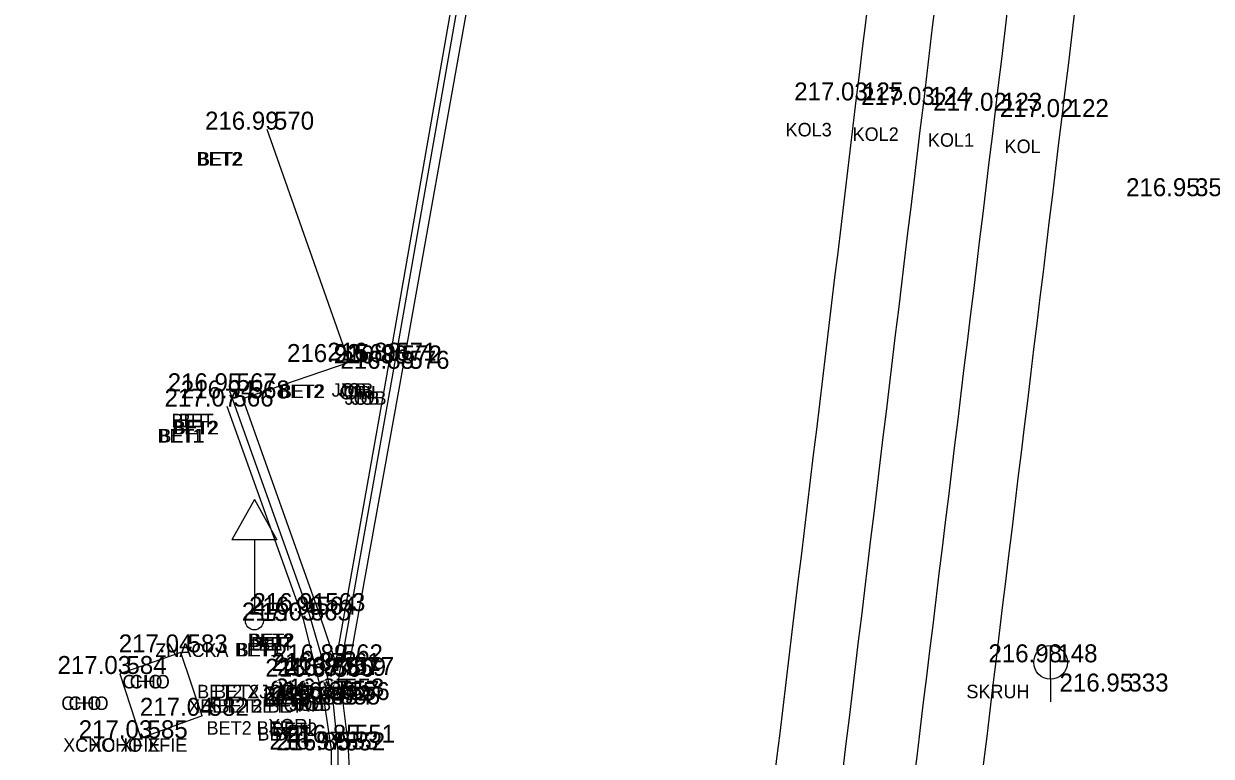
# Model space of a CAD drawing. Extents: x -471047 to -470889, y -1102859 to -1102000.
# Drawn here: x -471013.41 to -470987.01, y -1102709.11 to -1102692.81 of the extents above; entities that cross this region are included whole.
import ezdxf

# ---------------------------------------------------------------- set-up
doc = ezdxf.new("R2010")
doc.units = 0
for name, color, linetype in [('Vrstva 1', 7, 'Continuous'), ('Vrstva 19', 7, 'Continuous'), ('Vrstva 20', 7, 'Continuous'), ('Vrstva 25', 7, 'Continuous'), ('Vrstva 34', 7, 'Continuous'), ('Vrstva 35', 7, 'Continuous'), ('Vrstva 36', 7, 'Continuous'), ('Vrstva 38', 7, 'Continuous'), ('Vrstva 5', 7, 'Continuous'), ('Vrstva 7', 7, 'Continuous'), ('Vrstva 8', 7, 'Continuous')]:
    doc.layers.add(name, color=color, linetype=linetype)

msp = doc.modelspace()

# ---------------------------------------------------------------- linework, layer by layer
at = {"layer": 'Vrstva 1'}
for points in [[(-471040.344, -1102858.385), (-471031.676, -1102846.187), (-471026.357, -1102838.629), (-471023.212, -1102833.975), (-471019.21, -1102827.465), (-471016.861, -1102823.272), (-471013.099, -1102815.912), (-471010.824, -1102810.955), (-471007.329, -1102802.292), (-471005.34, -1102796.515), (-471002.842, -1102787.838), (-471001.3, -1102780.997), (-471000.19, -1102774.713), (-470999.247, -1102768.204), (-470998.794, -1102764.784), (-470997.199, -1102751.812), (-470994.899, -1102732.807), (-470992.551, -1102713.262), (-470990.326, -1102694.887), (-470988.122, -1102676.57), (-470985.812, -1102657.305), (-470983.537, -1102638.407), (-470981.386, -1102620.622), (-470979.843, -1102608.014), (-470976.377, -1102579.253), (-470972.945, -1102550.69), (-470970.475, -1102530.206), (-470967.905, -1102508.801), (-470965.053, -1102485.131), (-470962.734, -1102465.9), (-470960.173, -1102444.812), (-470957.795, -1102425.103), (-470954.965, -1102401.839), (-470953.834, -1102392.574), (-470952.33, -1102379.985), (-470950.744, -1102366.853), (-470948.978, -1102352.106), (-470947.037, -1102335.844), (-470944.949, -1102318.462), (-470944.013, -1102310.745), (-470942.39, -1102297.267), (-470939.519, -1102273.45), (-470937.593, -1102257.43), (-470936.064, -1102244.81), (-470934.114, -1102228.634), (-470931.621, -1102207.856), (-470929.536, -1102190.857), (-470926.572, -1102166.31), (-470924.91, -1102152.663), (-470923.413, -1102140.333), (-470921.923, -1102127.669), (-470921.155, -1102120.084), (-470920.446, -1102109.574), (-470919.912, -1102099.137), (-470919.63, -1102088.981), (-470919.523, -1102081.193), (-470919.563, -1102070.395), (-470919.714, -1102064.236), (-470920.134, -1102054.704), (-470920.462, -1102047.615), (-470920.599, -1102044.52), (-470920.743, -1102041.873), (-470921.125, -1102034.455), (-470921.774, -1102030.337), (-470922.418, -1102027.787), (-470923.734, -1102023.93), (-470924.872, -1102021.434), (-470926.752, -1102018.182), (-470927.953, -1102016.45), (-470929.616, -1102014.424), (-470932.252, -1102011.756), (-470935.111, -1102009.425), (-470938.391, -1102007.371), (-470942.651, -1102005.401)], [(-471041.328, -1102857.18), (-471032.144, -1102844.242), (-471027.583, -1102837.763), (-471024.388, -1102833.028), (-471020.451, -1102826.6), (-471018.089, -1102822.378), (-471014.542, -1102815.445), (-471012.233, -1102810.418), (-471009.247, -1102803.108), (-471006.795, -1102796.098), (-471004.315, -1102787.532), (-471002.782, -1102780.723), (-471001.674, -1102774.458), (-471000.75, -1102768.095), (-471000.28, -1102764.601), (-470998.692, -1102751.741), (-470996.378, -1102732.635), (-470994.028, -1102713.058), (-470991.808, -1102694.749), (-470989.616, -1102676.447), (-470987.284, -1102657.013), (-470985.031, -1102638.272), (-470982.87, -1102620.431), (-470981.334, -1102607.933), (-470977.881, -1102579.263), (-470974.429, -1102550.492), (-470971.964, -1102530.054), (-470969.391, -1102508.607), (-470966.54, -1102484.984), (-470964.231, -1102465.853), (-470961.679, -1102444.752), (-470959.304, -1102425.078), (-470956.455, -1102401.634), (-470955.339, -1102392.489), (-470953.812, -1102379.71), (-470952.249, -1102366.808), (-470950.479, -1102352.023), (-470948.536, -1102335.868), (-470946.426, -1102318.233), (-470945.493, -1102310.531), (-470943.864, -1102297.013), (-470940.984, -1102273.071), (-470939.078, -1102257.195), (-470937.559, -1102244.684), (-470935.592, -1102228.353), (-470933.101, -1102207.653), (-470931.011, -1102190.57), (-470928.046, -1102166.021), (-470926.409, -1102152.578), (-470924.898, -1102140.121), (-470923.427, -1102127.544), (-470922.647, -1102119.826), (-470921.919, -1102109.229), (-470921.42, -1102099.134), (-470921.127, -1102089.016), (-470921.023, -1102081.453), (-470921.061, -1102070.468), (-470921.209, -1102064.314), (-470921.666, -1102053.966), (-470922.156, -1102043.345), (-470922.299, -1102039.934), (-470922.637, -1102034.36), (-470923.091, -1102031.241), (-470923.847, -1102028.247), (-470925.083, -1102024.594), (-470926.222, -1102022.086), (-470928.04, -1102018.943), (-470929.138, -1102017.357), (-470930.929, -1102015.175), (-470933.062, -1102013.049), (-470936.379, -1102010.368), (-470939.169, -1102008.662), (-470942.899, -1102006.906), (-470945.661, -1102005.908)], [(-471043.557, -1102855.955), (-471035.129, -1102844.026), (-471029.872, -1102836.499), (-471026.577, -1102831.578), (-471022.675, -1102825.415), (-471020.123, -1102821.053), (-471016.667, -1102814.59), (-471014.208, -1102809.45), (-471011.177, -1102802.451), (-471008.55, -1102795.333), (-471006.082, -1102787.209), (-471004.464, -1102780.376), (-471003.265, -1102774.167), (-471002.327, -1102767.948), (-471001.636, -1102762.527), (-471000.297, -1102751.605), (-470997.959, -1102732.524), (-470995.602, -1102712.802), (-470993.412, -1102694.623), (-470991.21, -1102676.17), (-470988.891, -1102656.857), (-470986.625, -1102638.083), (-470984.455, -1102620.195), (-470982.936, -1102607.733), (-470979.497, -1102579.223), (-470976.023, -1102550.279), (-470973.554, -1102529.822), (-470970.991, -1102508.497), (-470968.146, -1102484.787), (-470965.835, -1102465.72), (-470963.284, -1102444.529), (-470960.91, -1102424.942), (-470958.043, -1102401.343), (-470956.946, -1102392.356), (-470955.396, -1102379.408), (-470953.851, -1102366.636), (-470952.049, -1102351.733), (-470950.124, -1102335.611), (-470948.034, -1102318.083), (-470947.094, -1102310.328), (-470945.421, -1102296.51), (-470942.58, -1102272.848), (-470940.675, -1102256.948), (-470939.176, -1102244.526), (-470937.187, -1102228.174), (-470934.708, -1102207.467), (-470932.621, -1102190.433), (-470929.634, -1102165.778), (-470928.004, -1102152.415), (-470926.45, -1102139.595), (-470925.003, -1102127.418), (-470924.249, -1102119.695), (-470923.515, -1102109.093), (-470923.018, -1102099.069), (-470922.711, -1102088.911), (-470922.643, -1102081.356), (-470922.797, -1102070.414), (-470923.018, -1102064.454), (-470923.52, -1102053.203), (-470923.823, -1102047.529), (-470924.123, -1102041.506), (-470924.462, -1102037.486), (-470924.934, -1102031.904), (-470925.664, -1102028.672), (-470926.771, -1102025.506), (-470927.959, -1102022.914), (-470929.674, -1102020.028), (-470930.76, -1102018.498), (-470932.447, -1102016.478), (-470935.215, -1102013.816), (-470937.644, -1102011.98), (-470940.381, -1102010.371), (-470943.968, -1102008.669), (-470947.145, -1102007.524), (-470950.874, -1102006.74)], [(-471044.756, -1102855.056), (-471036.376, -1102843.177), (-471031.167, -1102835.741), (-471027.859, -1102830.8), (-471023.934, -1102824.593), (-471021.43, -1102820.312), (-471018.011, -1102813.91), (-471015.536, -1102808.75), (-471012.578, -1102801.897), (-471009.95, -1102794.77), (-471007.561, -1102786.914), (-471005.936, -1102780.074), (-471004.727, -1102773.818), (-471003.828, -1102767.827), (-471003.121, -1102762.345), (-471001.787, -1102751.467), (-470999.446, -1102732.348), (-470997.073, -1102712.539), (-470994.902, -1102694.521), (-470992.696, -1102676.023), (-470990.376, -1102656.68), (-470988.131, -1102638.071), (-470985.947, -1102620.018), (-470984.417, -1102607.512), (-470980.993, -1102579.08), (-470977.514, -1102550.137), (-470975.048, -1102529.649), (-470972.488, -1102508.37), (-470969.618, -1102484.508), (-470967.34, -1102465.669), (-470964.767, -1102444.39), (-470962.402, -1102424.781), (-470959.534, -1102401.193), (-470958.432, -1102392.151), (-470956.883, -1102379.208), (-470955.335, -1102366.424), (-470953.535, -1102351.506), (-470951.606, -1102335.399), (-470949.519, -1102317.94), (-470948.575, -1102310.159), (-470946.889, -1102296.144), (-470944.056, -1102272.618), (-470942.139, -1102256.659), (-470940.657, -1102244.341), (-470938.638, -1102227.749), (-470936.19, -1102207.298), (-470934.102, -1102190.255), (-470931.124, -1102165.639), (-470929.492, -1102152.254), (-470927.915, -1102139.252), (-470926.46, -1102127.103), (-470925.74, -1102119.604), (-470925.012, -1102108.913), (-470924.523, -1102099.054), (-470924.217, -1102088.866), (-470924.148, -1102081.334), (-470924.301, -1102070.391), (-470924.518, -1102064.43), (-470924.97, -1102054.435), (-470925.588, -1102041.569), (-470925.963, -1102035.313), (-470926.405, -1102032.225), (-470927.078, -1102029.198), (-470928.123, -1102026.148), (-470929.318, -1102023.558), (-470930.84, -1102020.97), (-470931.868, -1102019.515), (-470933.443, -1102017.605), (-470936.26, -1102014.885), (-470938.429, -1102013.255), (-470941.213, -1102011.639), (-470944.847, -1102009.927), (-470947.723, -1102008.912), (-470951.444, -1102008.161), (-470954.511, -1102007.931), (-470957.895, -1102008.041)]]:
    msp.add_spline(points, degree=3, dxfattribs=at)
at = {"layer": 'Vrstva 19'}
for p, q in [((-471008.287, -1102703.398), (-471008.787, -1102704.298)), ((-471008.287, -1102703.398), (-471007.787, -1102704.298)), ((-471007.787, -1102704.298), (-471008.787, -1102704.298)), ((-471008.287, -1102704.298), (-471008.287, -1102705.898))]:
    msp.add_line(p, q, dxfattribs=at)
msp.add_circle((-471008.287, -1102706.098), 0.2, dxfattribs=at)
at = {"layer": 'Vrstva 20'}
for p, q in [((-471005.165, -1102700.374), (-471003.539, -1102691.123)), ((-471006.404, -1102707.324), (-471005.165, -1102700.374)), ((-471006.439, -1102707.78), (-471006.404, -1102707.324))]:
    msp.add_line(p, q, dxfattribs=at)
at = {"layer": 'Vrstva 25'}
for q in [(-470990.583, -1102706.647), (-470990.583, -1102707.897)]:
    msp.add_line((-470990.583, -1102707.397), q, dxfattribs=at)
msp.add_circle((-470990.583, -1102707.022), 0.375, dxfattribs=at)
at = {"layer": 'Vrstva 34'}
for p, q in [((-470994.9, -1102694.52), (-470994.9, -1102694.52)), ((-470993.41, -1102694.62), (-470993.41, -1102694.62)), ((-470991.81, -1102694.75), (-470991.81, -1102694.75)), ((-470990.33, -1102694.89), (-470990.33, -1102694.89)), ((-471008, -1102695.17), (-471008, -1102695.17)), ((-470987.52, -1102696.65), (-470987.52, -1102696.65)), ((-471006.18, -1102700.34), (-471006.18, -1102700.34)), ((-471005.28, -1102700.31), (-471005.28, -1102700.31)), ((-471005.16, -1102700.37), (-471005.16, -1102700.37)), ((-471004.99, -1102700.49), (-471004.99, -1102700.49)), ((-471008.83, -1102700.99), (-471008.83, -1102700.99)), ((-471008.54, -1102701.15), (-471008.54, -1102701.15)), ((-471008.9, -1102701.33), (-471008.9, -1102701.33)), ((-471006.86, -1102705.88), (-471006.86, -1102705.88)), ((-471008.29, -1102706.1), (-471008.29, -1102706.1)), ((-471007.18, -1102706.09), (-471007.18, -1102706.09)), ((-471007.06, -1102705.96), (-471007.06, -1102705.96)), ((-471009.92, -1102706.8), (-471009.92, -1102706.8)), ((-471006.52, -1102707.21), (-471006.52, -1102707.21)), ((-471006.47, -1102707.02), (-471006.47, -1102707.02)), ((-470990.58, -1102707.02), (-470990.58, -1102707.02)), ((-471011.28, -1102707.28), (-471011.28, -1102707.28)), ((-471006.66, -1102707.34), (-471006.66, -1102707.34)), ((-471006.4, -1102707.32), (-471006.4, -1102707.32)), ((-471006.22, -1102707.3), (-471006.22, -1102707.3)), ((-471006.44, -1102707.78), (-471006.44, -1102707.78)), ((-470989, -1102707.67), (-470989, -1102707.67)), ((-471006.72, -1102707.96), (-471006.72, -1102707.96)), ((-471006.55, -1102707.83), (-471006.55, -1102707.83)), ((-471006.53, -1102707.96), (-471006.53, -1102707.96)), ((-471006.32, -1102707.86), (-471006.32, -1102707.86)), ((-471009.45, -1102708.21), (-471009.45, -1102708.21)), ((-471010.81, -1102708.71), (-471010.81, -1102708.71)), ((-471006.2, -1102708.81), (-471006.2, -1102708.81)), ((-471006.57, -1102708.96), (-471006.57, -1102708.96)), ((-471006.42, -1102708.98), (-471006.42, -1102708.98))]:
    msp.add_line(p, q, dxfattribs=at)
at = {"layer": 'Vrstva 5'}
for p, q in [((-471006.18, -1102700.34), (-471008.003, -1102695.166)), ((-471008.541, -1102701.149), (-471006.18, -1102700.34)), ((-471006.859, -1102705.88), (-471008.541, -1102701.149)), ((-471006.472, -1102707.022), (-471006.859, -1102705.88)), ((-471006.658, -1102707.338), (-471006.518, -1102707.212)), ((-471006.518, -1102707.212), (-471006.472, -1102707.022)), ((-471006.316, -1102707.864), (-471006.549, -1102707.828)), ((-471006.203, -1102708.812), (-471006.316, -1102707.864)), ((-471006.145, -1102709.904), (-471006.203, -1102708.812))]:
    msp.add_line(p, q, dxfattribs=at)
at = {"layer": 'Vrstva 7'}
for p, q in [((-471007.184, -1102706.087), (-471008.895, -1102701.332)), ((-471006.718, -1102707.963), (-471007.184, -1102706.087)), ((-471006.573, -1102708.962), (-471006.718, -1102707.963)), ((-471006.576, -1102709.992), (-471006.573, -1102708.962))]:
    msp.add_line(p, q, dxfattribs=at)
at = {"layer": 'Vrstva 8'}
for p, q in [((-471005.28, -1102700.312), (-471003.66, -1102691.025)), ((-471003.31, -1102691.08), (-471004.991, -1102700.491)), ((-471006.472, -1102707.022), (-471005.28, -1102700.312)), ((-471004.991, -1102700.491), (-471006.223, -1102707.303)), ((-471007.064, -1102705.959), (-471008.83, -1102700.988)), ((-471006.658, -1102707.338), (-471007.064, -1102705.959)), ((-471009.922, -1102706.805), (-471011.275, -1102707.279)), ((-471009.447, -1102708.208), (-471009.922, -1102706.805)), ((-471011.275, -1102707.279), (-471010.811, -1102708.707)), ((-471006.549, -1102707.828), (-471006.658, -1102707.338)), ((-471006.528, -1102707.959), (-471006.549, -1102707.828)), ((-471006.421, -1102708.98), (-471006.528, -1102707.959)), ((-471009.447, -1102708.208), (-471010.811, -1102708.707)), ((-471006.424, -1102710.01), (-471006.421, -1102708.98))]:
    msp.add_line(p, q, dxfattribs=at)

# ---------------------------------------------------------------- texts
at = {"layer": 'Vrstva 35'}
for s, p in [('KOL3', (-470996.475, -1102695.32)), ('KOL2', (-470994.985, -1102695.42)), ('KOL1', (-470993.31, -1102695.55)), ('KOL', (-470991.605, -1102695.69)), ('BET2', (-471009.575, -1102695.97)), ('BET2', (-471009.541, -1102695.97)), ('BET2', (-471007.755, -1102701.14)), ('BET2', (-471007.721, -1102701.14)), ('JOB', (-471006.569, -1102701.11)), ('JOB', (-471006.419, -1102701.11)), ('ORI', (-471006.398, -1102701.17)), ('ORI', (-471006.299, -1102701.17)), ('JOB', (-471006.279, -1102701.29)), ('JOB', (-471006.129, -1102701.29)), ('BET', (-471010.13, -1102701.79)), ('BET2', (-471010.115, -1102701.95)), ('BET2', (-471010.081, -1102701.95)), ('BET', (-471009.969, -1102701.79)), ('BET1', (-471010.442, -1102702.13)), ('BET1', (-471010.4, -1102702.13)), ('BET2', (-471008.435, -1102706.68)), ('BET2', (-471008.401, -1102706.68)), ('BET', (-471008.36, -1102706.76)), ('BET', (-471008.199, -1102706.76)), ('ZNACKA', (-471010.49, -1102706.9)), ('BET1', (-471008.722, -1102706.89)), ('BET1', (-471008.68, -1102706.89)), ('CHO', (-471011.221, -1102707.6)), ('CHO', (-471011.059, -1102707.6)), ('BET2 XJOB', (-471009.559, -1102707.82)), ('BET2 XJOB', (-471009.185, -1102707.82)), ('SKRUH', (-470992.455, -1102707.82)), ('CHO', (-471012.581, -1102708.08)), ('CHO', (-471012.419, -1102708.08)), ('BET2', (-471008.095, -1102708.01)), ('BET2', (-471008.061, -1102708.01)), ('JOB', (-471007.509, -1102708.1)), ('JOB', (-471007.359, -1102708.1)), ('XBET2 BET', (-471009.76, -1102708.14)), ('XBET2 BET', (-471009.375, -1102708.14)), ('ORI', (-471007.638, -1102708.12)), ('XORI', (-471007.978, -1102708.58)), ('BET2 BET', (-471009.35, -1102708.63)), ('BET1', (-471008.22, -1102708.76)), ('BET2', (-471007.895, -1102708.66)), ('BET', (-471007.83, -1102708.76)), ('XCHO XFIE', (-471012.538, -1102709.01)), ('XCHO XFIE', (-471011.939, -1102709.01))]:
    msp.add_text(s, height=0.3, dxfattribs=at).set_placement(p)
at = {"layer": 'Vrstva 36'}
for s, p in [(' 125', (-470994.9, -1102694.52)), (' 124', (-470993.41, -1102694.62)), (' 123', (-470991.81, -1102694.75)), (' 122', (-470990.33, -1102694.89)), (' 570', (-471008, -1102695.17)), (' 351', (-470987.52, -1102696.65)), (' 569', (-471006.18, -1102700.34)), (' 571', (-471005.28, -1102700.31)), (' 572', (-471005.16, -1102700.37)), (' 576', (-471004.99, -1102700.49)), (' 567', (-471008.83, -1102700.99)), (' 566', (-471008.9, -1102701.33)), (' 568', (-471008.54, -1102701.15)), (' 565', (-471007.18, -1102706.09)), (' 564', (-471007.06, -1102705.96)), (' 563', (-471006.86, -1102705.88)), (' 15', (-471008.29, -1102706.1)), (' 583', (-471009.92, -1102706.8)), (' 562', (-471006.47, -1102707.02)), (' 148', (-470990.58, -1102707.02)), (' 584', (-471011.28, -1102707.28)), (' 560', (-471006.66, -1102707.34)), (' 561', (-471006.52, -1102707.21)), (' 559', (-471006.4, -1102707.32)), (' 577', (-471006.22, -1102707.3)), (' 333', (-470989, -1102707.67)), (' 557', (-471006.55, -1102707.83)), (' 558', (-471006.44, -1102707.78)), (' 556', (-471006.32, -1102707.86)), (' 554', (-471006.72, -1102707.96)), (' 555', (-471006.53, -1102707.96)), (' 582', (-471009.45, -1102708.21)), (' 585', (-471010.81, -1102708.71)), (' 553', (-471006.57, -1102708.96)), (' 552', (-471006.42, -1102708.98)), (' 551', (-471006.2, -1102708.81))]:
    msp.add_text(s, height=0.4, dxfattribs=at).set_placement(p)
at = {"layer": 'Vrstva 38'}
for s, p in [('217.03 ', (-470996.283, -1102694.52)), ('217.03 ', (-470994.793, -1102694.62)), ('217.02 ', (-470993.191, -1102694.75)), ('217.02 ', (-470991.711, -1102694.89)), ('216.99 ', (-471009.384, -1102695.17)), ('216.95 ', (-470988.904, -1102696.65)), ('216.92 ', (-471007.561, -1102700.34)), ('216.88 ', (-471006.664, -1102700.31)), ('216.86 ', (-471006.52, -1102700.37)), ('216.88 ', (-471006.374, -1102700.49)), ('216.95 ', (-471010.214, -1102700.99)), ('217.07 ', (-471010.283, -1102701.33)), ('216.94 ', (-471009.922, -1102701.15)), ('217.03 ', (-471008.563, -1102706.09)), ('216.90 ', (-471008.403, -1102705.96)), ('216.91 ', (-471008.33, -1102705.88)), ('217.04 ', (-471011.302, -1102706.8)), ('216.89 ', (-471007.854, -1102707.02)), ('216.98 ', (-470991.964, -1102707.02)), ('217.03 ', (-471012.663, -1102707.28)), ('216.87 ', (-471008.043, -1102707.34)), ('216.87 ', (-471007.903, -1102707.21)), ('216.87 ', (-471007.783, -1102707.32)), ('216.85 ', (-471007.604, -1102707.3)), ('216.95 ', (-470990.384, -1102707.67)), ('216.85 ', (-471007.934, -1102707.83)), ('216.87 ', (-471007.823, -1102707.78)), ('216.86 ', (-471007.68, -1102707.86)), ('216.98 ', (-471008.104, -1102707.96)), ('216.84 ', (-471007.912, -1102707.96)), ('217.04 ', (-471010.832, -1102708.21)), ('217.03 ', (-471012.193, -1102708.71)), ('216.97 ', (-471007.953, -1102708.96)), ('216.85 ', (-471007.804, -1102708.98)), ('216.85 ', (-471007.584, -1102708.81))]:
    msp.add_text(s, height=0.4, dxfattribs=at).set_placement(p)

doc.saveas('drawing.dxf')
